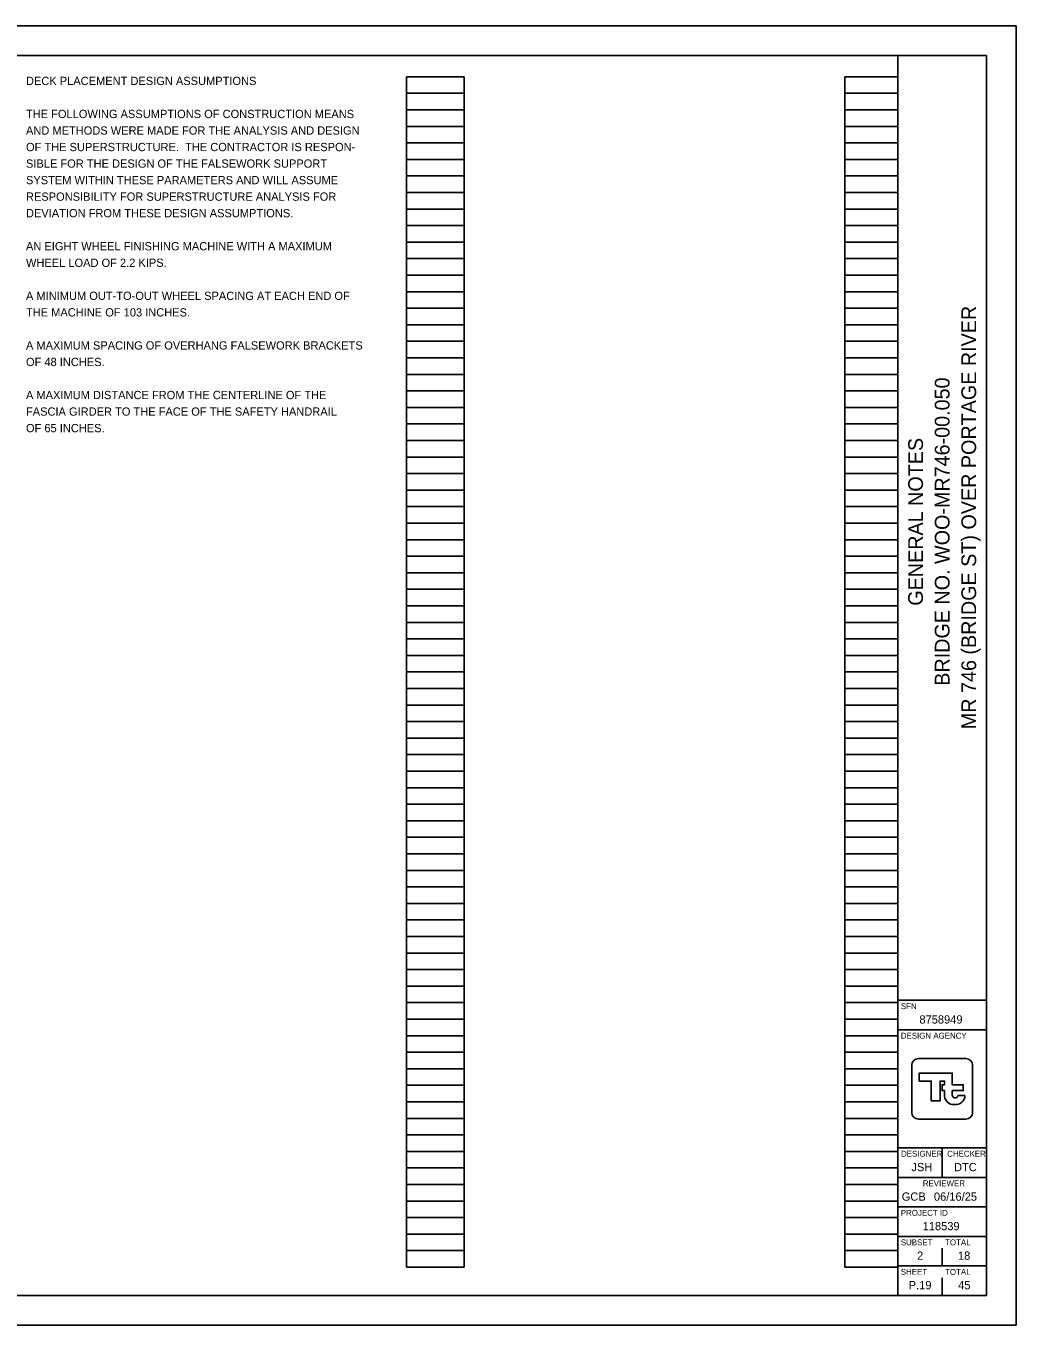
# Model space of a CAD drawing. Extents: x 0 to 34, y 0 to 22.
# Drawn here: x 17.24 to 34, y 0 to 22 of the extents above; entities that cross this region are included whole.
import ezdxf

# ---------------------------------------------------------------- set-up
doc = ezdxf.new("R2010")
doc.units = 0
for name, color, linetype in [('SH_Border', 7, 'Continuous'), ('SH_Cut_Line', 7, 'Continuous'), ('SH_Data', 7, 'Continuous'), ('SH_Text', 7, 'Continuous')]:
    doc.layers.add(name, color=color, linetype=linetype)

msp = doc.modelspace()

# ---------------------------------------------------------------- linework, layer by layer
at = {"layer": 'SH_Border'}
for p, q in [((32, 0.5), (32, 21.5)), ((32, 5.5), (33.5, 5.5)), ((32, 5), (33.5, 5)), ((32, 3), (33.5, 3)), ((32.75, 3), (32.75, 2.5)), ((32, 2.5), (33.5, 2.5)), ((32, 2), (33.5, 2)), ((32, 1.5), (33.5, 1.5)), ((32, 1), (33.5, 1))]:
    msp.add_line(p, q, dxfattribs=at)
msp.add_lwpolyline([(1.5, 21.5), (33.5, 21.5), (33.5, 0.5), (1.5, 0.5)], close=True, dxfattribs=at)
at = {"layer": 'SH_Cut_Line'}
msp.add_lwpolyline([(0, 0), (34, 0), (34, 22), (0, 22)], close=True, dxfattribs=at)
at = {"layer": 'SH_Data'}
for p, q in [((23.68, 0.98), (23.68, 21.14)), ((23.68, 21.14), (24.66, 21.14)), ((24.66, 0.98), (24.66, 21.14)), ((31.1, 0.98), (31.1, 21.14)), ((31.1, 21.14), (32, 21.14)), ((32, 0.98), (32, 21.14)), ((23.68, 20.86), (24.66, 20.86)), ((31.1, 20.86), (32, 20.86)), ((23.68, 20.58), (24.66, 20.58)), ((31.1, 20.58), (32, 20.58)), ((23.68, 20.3), (24.66, 20.3)), ((31.1, 20.3), (32, 20.3)), ((23.68, 20.02), (24.66, 20.02)), ((31.1, 20.02), (32, 20.02)), ((23.68, 19.74), (24.66, 19.74)), ((31.1, 19.74), (32, 19.74)), ((23.68, 19.46), (24.66, 19.46)), ((31.1, 19.46), (32, 19.46)), ((23.68, 19.18), (24.66, 19.18)), ((31.1, 19.18), (32, 19.18)), ((23.68, 18.9), (24.66, 18.9)), ((31.1, 18.9), (32, 18.9)), ((23.68, 18.62), (24.66, 18.62)), ((31.1, 18.62), (32, 18.62)), ((23.68, 18.34), (24.66, 18.34)), ((31.1, 18.34), (32, 18.34)), ((23.68, 18.06), (24.66, 18.06)), ((31.1, 18.06), (32, 18.06)), ((23.68, 17.78), (24.66, 17.78)), ((31.1, 17.78), (32, 17.78)), ((23.68, 17.5), (24.66, 17.5)), ((31.1, 17.5), (32, 17.5)), ((23.68, 17.22), (24.66, 17.22)), ((31.1, 17.22), (32, 17.22)), ((23.68, 16.94), (24.66, 16.94)), ((31.1, 16.94), (32, 16.94)), ((23.68, 16.66), (24.66, 16.66)), ((31.1, 16.66), (32, 16.66)), ((23.68, 16.38), (24.66, 16.38)), ((31.1, 16.38), (32, 16.38)), ((23.68, 16.1), (24.66, 16.1)), ((31.1, 16.1), (32, 16.1)), ((23.68, 15.82), (24.66, 15.82)), ((31.1, 15.82), (32, 15.82)), ((23.68, 15.54), (24.66, 15.54)), ((31.1, 15.54), (32, 15.54)), ((23.68, 15.26), (24.66, 15.26)), ((31.1, 15.26), (32, 15.26)), ((23.68, 14.98), (24.66, 14.98)), ((31.1, 14.98), (32, 14.98)), ((23.68, 14.7), (24.66, 14.7)), ((31.1, 14.7), (32, 14.7)), ((23.68, 14.42), (24.66, 14.42)), ((31.1, 14.42), (32, 14.42)), ((23.68, 14.14), (24.66, 14.14)), ((31.1, 14.14), (32, 14.14)), ((23.68, 13.86), (24.66, 13.86)), ((31.1, 13.86), (32, 13.86)), ((23.68, 13.58), (24.66, 13.58)), ((31.1, 13.58), (32, 13.58)), ((23.68, 13.3), (24.66, 13.3)), ((31.1, 13.3), (32, 13.3)), ((23.68, 13.02), (24.66, 13.02)), ((31.1, 13.02), (32, 13.02)), ((23.68, 12.74), (24.66, 12.74)), ((31.1, 12.74), (32, 12.74)), ((23.68, 12.46), (24.66, 12.46)), ((31.1, 12.46), (32, 12.46)), ((23.68, 12.18), (24.66, 12.18)), ((31.1, 12.18), (32, 12.18)), ((23.68, 11.9), (24.66, 11.9)), ((31.1, 11.9), (32, 11.9)), ((23.68, 11.62), (24.66, 11.62)), ((31.1, 11.62), (32, 11.62)), ((23.68, 11.34), (24.66, 11.34)), ((31.1, 11.34), (32, 11.34)), ((23.68, 11.06), (24.66, 11.06)), ((31.1, 11.06), (32, 11.06)), ((23.68, 10.78), (24.66, 10.78)), ((31.1, 10.78), (32, 10.78)), ((23.68, 10.5), (24.66, 10.5)), ((31.1, 10.5), (32, 10.5)), ((23.68, 10.22), (24.66, 10.22)), ((31.1, 10.22), (32, 10.22)), ((23.68, 9.94), (24.66, 9.94)), ((31.1, 9.94), (32, 9.94)), ((23.68, 9.66), (24.66, 9.66)), ((31.1, 9.66), (32, 9.66)), ((23.68, 9.38), (24.66, 9.38)), ((31.1, 9.38), (32, 9.38)), ((23.68, 9.1), (24.66, 9.1)), ((31.1, 9.1), (32, 9.1)), ((23.68, 8.82), (24.66, 8.82)), ((31.1, 8.82), (32, 8.82)), ((23.68, 8.54), (24.66, 8.54)), ((31.1, 8.54), (32, 8.54)), ((23.68, 8.26), (24.66, 8.26)), ((31.1, 8.26), (32, 8.26)), ((23.68, 7.98), (24.66, 7.98)), ((31.1, 7.98), (32, 7.98)), ((23.68, 7.7), (24.66, 7.7)), ((31.1, 7.7), (32, 7.7)), ((23.68, 7.42), (24.66, 7.42)), ((31.1, 7.42), (32, 7.42)), ((23.68, 7.14), (24.66, 7.14)), ((31.1, 7.14), (32, 7.14)), ((23.68, 6.86), (24.66, 6.86)), ((31.1, 6.86), (32, 6.86)), ((23.68, 6.58), (24.66, 6.58)), ((31.1, 6.58), (32, 6.58)), ((23.68, 6.3), (24.66, 6.3)), ((31.1, 6.3), (32, 6.3)), ((23.68, 6.02), (24.66, 6.02)), ((31.1, 6.02), (32, 6.02)), ((23.68, 5.74), (24.66, 5.74)), ((31.1, 5.74), (32, 5.74)), ((23.68, 5.46), (24.66, 5.46)), ((31.1, 5.46), (32, 5.46)), ((23.68, 5.18), (24.66, 5.18)), ((31.1, 5.18), (32, 5.18)), ((23.68, 4.9), (24.66, 4.9)), ((31.1, 4.9), (32, 4.9)), ((23.68, 4.62), (24.66, 4.62)), ((31.1, 4.62), (32, 4.62)), ((23.68, 4.34), (24.66, 4.34)), ((31.1, 4.34), (32, 4.34)), ((23.68, 4.06), (24.66, 4.06)), ((31.1, 4.06), (32, 4.06)), ((32.75, 4), (32.75, 4)), ((23.68, 3.78), (24.66, 3.78)), ((31.1, 3.78), (32, 3.78)), ((32.791, 3.915), (32.791, 3.915)), ((33.136, 3.885), (33.015, 3.885)), ((23.68, 3.5), (24.66, 3.5)), ((31.1, 3.5), (32, 3.5)), ((23.68, 3.22), (24.66, 3.22)), ((31.1, 3.22), (32, 3.22)), ((23.68, 2.94), (24.66, 2.94)), ((31.1, 2.94), (32, 2.94)), ((23.68, 2.66), (24.66, 2.66)), ((31.1, 2.66), (32, 2.66)), ((23.68, 2.38), (24.66, 2.38)), ((31.1, 2.38), (32, 2.38)), ((23.68, 2.1), (24.66, 2.1)), ((31.1, 2.1), (32, 2.1)), ((23.68, 1.82), (24.66, 1.82)), ((31.1, 1.82), (32, 1.82)), ((23.68, 1.54), (24.66, 1.54)), ((31.1, 1.54), (32, 1.54)), ((23.68, 1.26), (24.66, 1.26)), ((31.1, 1.26), (32, 1.26)), ((32.75, 1), (32.75, 1.3)), ((23.68, 0.98), (24.66, 0.98)), ((31.1, 0.98), (32, 0.98)), ((32.375, 0.675), (32.375, 0.675)), ((32.75, 0.5), (32.75, 0.8))]:
    msp.add_line(p, q, dxfattribs=at)
for points in [[(32.236, 3.599), (32.236, 4.401)], [(32.348, 4.514), (33.152, 4.514)], [(33.264, 4.401), (33.264, 3.599)], [(32.922, 3.899), (32.922, 3.97), (33.107, 3.97), (33.107, 4.068), (32.922, 4.068), (32.922, 4.268), (32.361, 4.268), (32.361, 4.132), (32.566, 4.132), (32.566, 3.794), (32.715, 3.794), (32.715, 4.13), (32.79, 4.13), (32.79, 4.068), (32.748, 4.068), (32.748, 3.97), (32.79, 3.97), (32.79, 3.915), (32.791, 3.915)], [(33.152, 3.486), (32.348, 3.486)]]:
    msp.add_lwpolyline(points, dxfattribs=at)
for centre, radius, start, end in [((32.348, 4.401), 0.113, 90, 180), ((33.152, 4.401), 0.113, 360, 90), ((32.949, 3.892), 0.16, 171.8856, 274.8323), ((32.968, 3.892), 0.0473, 171.8856, 350.9243), ((32.976, 3.892), 0.16, 265.1677, 357.3201), ((32.348, 3.599), 0.113, 180, 270), ((33.152, 3.599), 0.113, 270, 360)]:
    msp.add_arc(centre, radius, start, end, dxfattribs=at)

# ---------------------------------------------------------------- texts
for s, p in [('MR 746 (BRIDGE ST) OVER PORTAGE RIVER', (33.325, 10.091)), ('BRIDGE NO. WOO-MR746-00.050', (32.875, 10.827)), ('GENERAL NOTES', (32.425, 12.182))]:
    msp.add_text(s, height=0.25, rotation=90, dxfattribs=at).set_placement(p)
for s, height, p in [('SFN', 0.1, (32.05, 5.35)), ('8758949', 0.14, (32.365, 5.105)), ('DESIGN AGENCY', 0.1, (32.05, 4.85)), ('DESIGNER', 0.1, (32.054, 2.85)), ('CHECKER', 0.1, (32.835, 2.85)), ('JSH', 0.14, (32.23, 2.605)), ('DTC', 0.14, (32.951, 2.605)), ('REVIEWER', 0.1, (32.422, 2.35)), ('GCB', 0.14, (32.066, 2.105)), ('06/16/25', 0.14, (32.611, 2.105)), ('PROJECT ID', 0.1, (32.05, 1.85)), ('118539', 0.14, (32.42, 1.605)), ('SUBSET', 0.1, (32.05, 1.35)), ('TOTAL', 0.1, (32.8, 1.35)), ('2', 0.14, (32.325, 1.105)), ('18', 0.14, (33.018, 1.105)), ('SHEET', 0.1, (32.05, 0.85)), ('TOTAL', 0.1, (32.8, 0.85)), ('P.19', 0.14, (32.184, 0.605)), ('45', 0.14, (33.02, 0.605))]:
    msp.add_text(s, height=height, dxfattribs=at).set_placement(p)
at = {"layer": 'SH_Text'}
for s, p in [('DECK PLACEMENT DESIGN ASSUMPTIONS', (17.24, 21)), ('THE FOLLOWING ASSUMPTIONS OF CONSTRUCTION MEANS', (17.24, 20.44)), ('AND METHODS WERE MADE FOR THE ANALYSIS AND DESIGN', (17.24, 20.16)), ('OF THE SUPERSTRUCTURE.  THE CONTRACTOR IS RESPON-', (17.24, 19.88)), ('SIBLE FOR THE DESIGN OF THE FALSEWORK SUPPORT', (17.24, 19.6)), ('SYSTEM WITHIN THESE PARAMETERS AND WILL ASSUME', (17.24, 19.32)), ('RESPONSIBILITY FOR SUPERSTRUCTURE ANALYSIS FOR', (17.24, 19.04)), ('DEVIATION FROM THESE DESIGN ASSUMPTIONS.', (17.24, 18.76)), ('AN EIGHT WHEEL FINISHING MACHINE WITH A MAXIMUM', (17.24, 18.2)), ('WHEEL LOAD OF 2.2 KIPS.', (17.24, 17.92)), ('A MINIMUM OUT-TO-OUT WHEEL SPACING AT EACH END OF', (17.24, 17.36)), ('THE MACHINE OF 103 INCHES.', (17.24, 17.08)), ('A MAXIMUM SPACING OF OVERHANG FALSEWORK BRACKETS', (17.24, 16.52)), ('OF 48 INCHES.', (17.24, 16.24)), ('A MAXIMUM DISTANCE FROM THE CENTERLINE OF THE', (17.24, 15.68)), ('FASCIA GIRDER TO THE FACE OF THE SAFETY HANDRAIL', (17.24, 15.4)), ('OF 65 INCHES.', (17.24, 15.12))]:
    msp.add_text(s, height=0.14, dxfattribs=at).set_placement(p)

doc.saveas('drawing.dxf')
